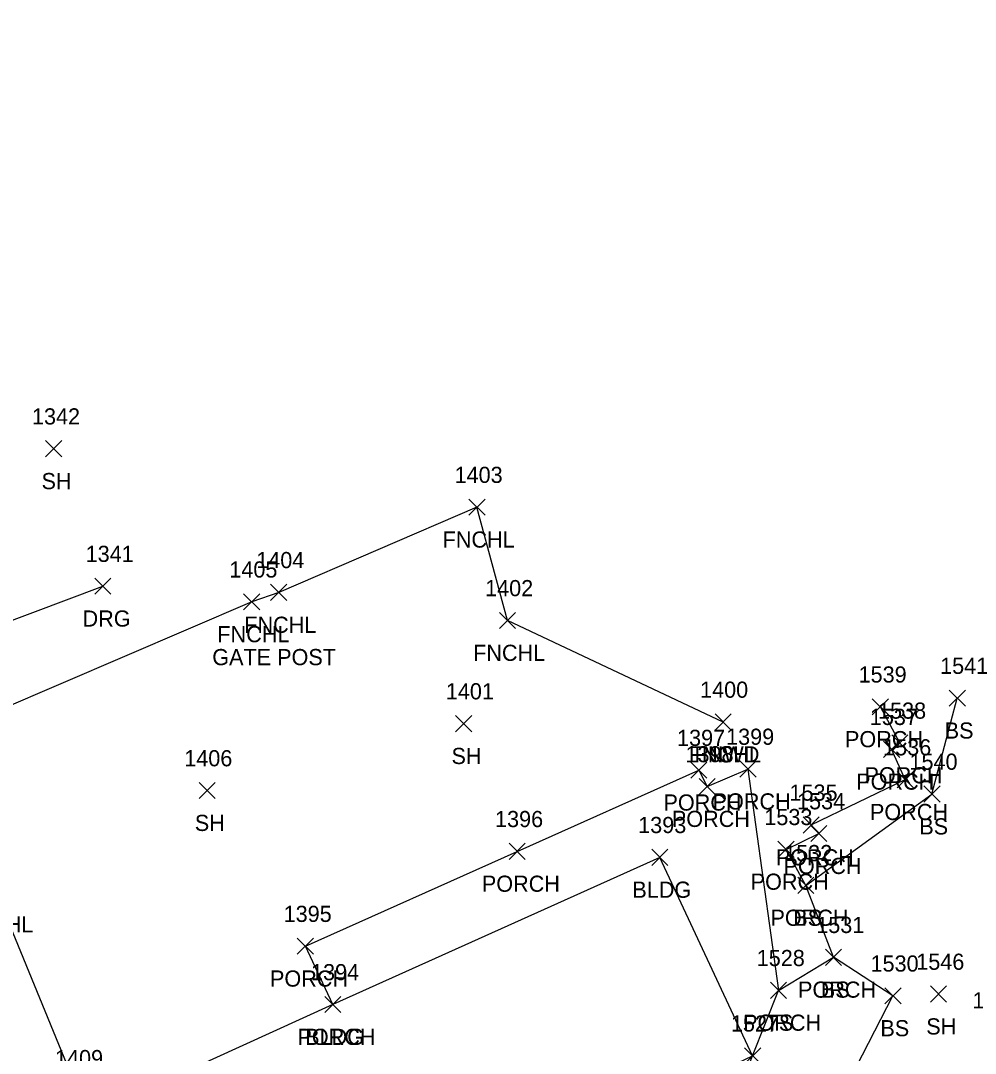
# Model space of a CAD drawing. Extents: x 1504228 to 1506103, y 437717 to 440106.
# Drawn here: x 1505212.8 to 1505331, y 438311.9 to 438439.6 of the extents above; entities that cross this region are included whole.
import ezdxf

# ---------------------------------------------------------------- set-up
doc = ezdxf.new("R2010")
doc.units = 0
for name, color, linetype in [('L_A', 7, 'Continuous'), ('L_C', 7, 'Continuous'), ('L_I', 7, 'Continuous'), ('L_TIC', 7, 'Continuous'), ('LBC', 7, 'Continuous'), ('LBF', 7, 'Continuous'), ('LELB', 7, 'Continuous'), ('LFNC', 7, 'Continuous'), ('R_A', 7, 'Continuous'), ('R_I', 7, 'Continuous'), ('R_TIC', 7, 'Continuous'), ('RDG', 7, 'Continuous')]:
    doc.layers.add(name, color=color, linetype=linetype)

msp = doc.modelspace()

# ---------------------------------------------------------------- linework, layer by layer
at = {"layer": 'L_TIC'}
for points in [[(1505215.93, 438385.69), (1505217.93, 438387.69)], [(1505217.93, 438385.69), (1505215.93, 438387.69)], [(1505268.3, 438378.46), (1505270.3, 438380.46)], [(1505270.3, 438378.46), (1505268.3, 438380.46)], [(1505243.77, 438367.92), (1505245.77, 438369.92)], [(1505245.77, 438367.92), (1505243.77, 438369.92)], [(1505240.43, 438366.76), (1505242.43, 438368.76)], [(1505242.43, 438366.76), (1505240.43, 438368.76)], [(1505272.09, 438364.45), (1505274.09, 438366.45)], [(1505274.09, 438364.45), (1505272.09, 438366.45)], [(1505327.74, 438354.84), (1505329.74, 438356.84)], [(1505329.74, 438354.84), (1505327.74, 438356.84)], [(1505318.22, 438353.77), (1505320.22, 438355.77)], [(1505320.22, 438353.77), (1505318.22, 438355.77)], [(1505266.66, 438351.69), (1505268.66, 438353.69)], [(1505268.66, 438351.69), (1505266.66, 438353.69)], [(1505298.77, 438351.89), (1505300.77, 438353.89)], [(1505300.77, 438351.89), (1505298.77, 438353.89)], [(1505298.77, 438351.89), (1505300.77, 438353.89)], [(1505300.77, 438351.89), (1505298.77, 438353.89)], [(1505320.63, 438349.3), (1505322.63, 438351.3)], [(1505322.63, 438349.3), (1505320.63, 438351.3)], [(1505319.61, 438348.52), (1505321.61, 438350.52)], [(1505321.61, 438348.52), (1505319.61, 438350.52)], [(1505295.76, 438345.93), (1505297.76, 438347.93)], [(1505297.76, 438345.93), (1505295.76, 438347.93)], [(1505301.83, 438346.07), (1505303.83, 438348.07)], [(1505303.83, 438346.07), (1505301.83, 438348.07)], [(1505321.3, 438344.76), (1505323.3, 438346.76)], [(1505323.3, 438344.76), (1505321.3, 438346.76)], [(1505234.91, 438343.41), (1505236.91, 438345.41)], [(1505236.91, 438343.41), (1505234.91, 438345.41)], [(1505296.79, 438343.91), (1505298.79, 438345.91)], [(1505298.79, 438343.91), (1505296.79, 438345.91)], [(1505324.6, 438342.98), (1505326.6, 438344.98)], [(1505326.6, 438342.98), (1505324.6, 438344.98)], [(1505309.66, 438339.16), (1505311.66, 438341.16)], [(1505311.66, 438339.16), (1505309.66, 438341.16)], [(1505310.61, 438338.09), (1505312.61, 438340.09)], [(1505312.61, 438338.09), (1505310.61, 438340.09)], [(1505273.28, 438335.89), (1505275.28, 438337.89)], [(1505275.28, 438335.89), (1505273.28, 438337.89)], [(1505290.94, 438335.15), (1505292.94, 438337.15)], [(1505292.94, 438335.15), (1505290.94, 438337.15)], [(1505290.94, 438335.15), (1505292.94, 438337.15)], [(1505292.94, 438335.15), (1505290.94, 438337.15)], [(1505306.55, 438336.14), (1505308.55, 438338.14)], [(1505308.55, 438336.14), (1505306.55, 438338.14)], [(1505309, 438331.68), (1505311, 438333.68)], [(1505311, 438331.68), (1505309, 438333.68)], [(1505309, 438331.68), (1505311, 438333.68)], [(1505311, 438331.68), (1505309, 438333.68)], [(1505247.07, 438324.16), (1505249.07, 438326.16)], [(1505249.07, 438324.16), (1505247.07, 438326.16)], [(1505312.41, 438322.79), (1505314.41, 438324.79)], [(1505314.41, 438322.79), (1505312.41, 438324.79)], [(1505312.41, 438322.79), (1505314.41, 438324.79)], [(1505314.41, 438322.79), (1505312.41, 438324.79)], [(1505305.61, 438318.7), (1505307.61, 438320.7)], [(1505307.61, 438318.7), (1505305.61, 438320.7)], [(1505305.61, 438318.7), (1505307.61, 438320.7)], [(1505307.61, 438318.7), (1505305.61, 438320.7)], [(1505319.78, 438318.02), (1505321.78, 438320.02)], [(1505321.78, 438318.02), (1505319.78, 438320.02)], [(1505325.41, 438318.24), (1505327.41, 438320.24)], [(1505327.41, 438318.24), (1505325.41, 438320.24)], [(1505250.46, 438316.95), (1505252.46, 438318.95)], [(1505252.46, 438316.95), (1505250.46, 438318.95)], [(1505250.46, 438316.95), (1505252.46, 438318.95)], [(1505252.46, 438316.95), (1505250.46, 438318.95)], [(1505302.41, 438310.6), (1505304.41, 438312.6)], [(1505304.41, 438310.6), (1505302.41, 438312.6)], [(1505302.41, 438310.6), (1505304.41, 438312.6)], [(1505304.41, 438310.6), (1505302.41, 438312.6)]]:
    msp.add_lwpolyline(points, dxfattribs=at)
at = {"layer": 'LBC'}
for points in [[(1505291.94, 438336.15), (1505251.46, 438317.95), (1505221.32, 438304.23), (1505215.36, 438301.39), (1505212.86, 438300.1), (1505216.77, 438291.38), (1505219.71, 438285.09), (1505224.14, 438275.75), (1505225.84, 438276.51), (1505226.05, 438276.61), (1505237.29, 438281.5), (1505257.32, 438290.64), (1505259.92, 438292.17), (1505266.3, 438278.35), (1505276.69, 438282.9), (1505286.75, 438287.54), (1505280.28, 438300.6), (1505303.41, 438311.6)], [(1505303.41, 438311.6), (1505291.94, 438336.15)]]:
    msp.add_lwpolyline(points, dxfattribs=at)
at = {"layer": 'LBF'}
msp.add_lwpolyline([(1505251.46, 438317.95), (1505248.07, 438325.16), (1505274.28, 438336.89), (1505296.76, 438346.93), (1505297.79, 438344.91), (1505302.83, 438347.07), (1505306.61, 438319.7), (1505313.41, 438323.79), (1505310, 438332.68), (1505307.55, 438337.14), (1505311.61, 438339.09), (1505310.66, 438340.16), (1505322.3, 438345.76), (1505320.61, 438349.52), (1505321.63, 438350.3), (1505319.22, 438354.77)], dxfattribs=at)
at = {"layer": 'LELB'}
for points in [[(1505310, 438332.68), (1505325.6, 438343.98), (1505328.74, 438355.84)], [(1505219.87, 438244.66), (1505224.21, 438246.43), (1505223.77, 438248.66), (1505222.66, 438251.45), (1505223.31, 438252.49), (1505228.98, 438251.31), (1505233.48, 438250.35), (1505246.94, 438254.41), (1505264.28, 438261.06), (1505277.62, 438265.2), (1505287.87, 438271.1), (1505299.61, 438285.63), (1505311.02, 438300.11), (1505320.78, 438319.02), (1505313.41, 438323.79)], [(1505233.95, 438258.18), (1505246, 438260.65), (1505261.61, 438268.97), (1505271.35, 438273.16), (1505281.01, 438281.22), (1505294.75, 438289.38), (1505303.41, 438311.6), (1505306.61, 438319.7)]]:
    msp.add_lwpolyline(points, dxfattribs=at)
at = {"layer": 'LFNC'}
msp.add_lwpolyline([(1505299.77, 438352.89), (1505273.09, 438365.45), (1505269.3, 438379.46), (1505244.77, 438368.92), (1505241.43, 438367.76), (1505202.02, 438350.84), (1505209.75, 438331.86), (1505219.87, 438307.32), (1505221.32, 438304.23)], dxfattribs=at)
at = {"layer": 'R_TIC'}
for points in [[(1505222.01, 438368.69), (1505224.01, 438370.69)], [(1505224.01, 438368.69), (1505222.01, 438370.69)]]:
    msp.add_lwpolyline(points, dxfattribs=at)
at = {"layer": 'RDG'}
msp.add_lwpolyline([(1505169.09, 438439.64), (1505176.6, 438437.44), (1505183.39, 438415.8), (1505189.12, 438396.31), (1505196.49, 438374.95), (1505201.15, 438361.5), (1505223.01, 438369.69)], dxfattribs=at)

# ---------------------------------------------------------------- texts
at = {"layer": 'L_A'}
for s, p in [('SH', (1505215.42, 438381.69)), ('FNCHL', (1505265.05, 438374.46)), ('FNCHL', (1505240.51, 438363.92)), ('FNCHL', (1505237.18, 438362.76)), ('FNCHL', (1505268.83, 438360.45)), ('BS', (1505327.18, 438350.84)), ('PORCH', (1505314.84, 438349.77)), ('FNCHL', (1505295.52, 438347.89)), ('FNWD', (1505296.23, 438347.89)), ('SH', (1505266.15, 438347.69)), ('PORCH', (1505317.25, 438345.3)), ('PORCH', (1505316.23, 438344.52)), ('PORCH', (1505292.38, 438341.93)), ('PORCH', (1505298.46, 438342.07)), ('PORCH', (1505317.93, 438340.76)), ('SH', (1505234.39, 438339.41)), ('PORCH', (1505293.42, 438339.91)), ('BS', (1505324.04, 438338.98)), ('PORCH', (1505306.28, 438335.16)), ('PORCH', (1505307.23, 438334.09)), ('PORCH', (1505269.91, 438331.89)), ('BLDG', (1505288.53, 438331.15)), ('BLDG', (1505288.53, 438331.15)), ('PORCH', (1505303.17, 438332.14)), ('PORCH', (1505305.62, 438327.68)), ('BS', (1505308.44, 438327.68)), ('FNCHL', (1505205.5, 438326.86)), ('PORCH', (1505243.69, 438320.16)), ('PORCH', (1505309.03, 438318.79)), ('BS', (1505311.85, 438318.79)), ('PORCH', (1505302.23, 438314.7)), ('TS', (1505305.02, 438314.7)), ('BS', (1505319.22, 438314.02)), ('SH', (1505324.9, 438314.24)), ('PORCH', (1505247.09, 438312.95)), ('BLDG', (1505248.05, 438312.95))]:
    msp.add_text(s, height=2, dxfattribs=at).set_placement(p)
at = {"layer": 'L_C'}
msp.add_text('GATE POST', height=2, dxfattribs=at).set_placement((1505236.55, 438359.92))
at = {"layer": 'L_I'}
for s, p in [('1342', (1505214.24, 438389.69)), ('1403', (1505266.53, 438382.46)), ('1405', (1505238.66, 438370.76)), ('1404', (1505241.99, 438371.92)), ('1402', (1505270.31, 438368.45)), ('1541', (1505326.61, 438358.84)), ('1539', (1505316.52, 438357.77)), ('1401', (1505265.45, 438355.69)), ('1400', (1505296.91, 438355.89)), ('1400', (1505296.91, 438355.89)), ('1538', (1505318.93, 438353.3)), ('1537', (1505317.91, 438352.52)), ('1397', (1505294.06, 438349.93)), ('1399', (1505300.13, 438350.07)), ('1398', (1505295.1, 438347.91)), ('1536', (1505319.56, 438348.76)), ('1406', (1505233.08, 438347.41)), ('1540', (1505322.82, 438346.98)), ('1535', (1505307.97, 438343.16)), ('1534', (1505308.91, 438342.09)), ('1533', (1505304.86, 438340.14)), ('1396', (1505271.54, 438339.89)), ('1393', (1505289.25, 438339.15)), ('1393', (1505289.25, 438339.15)), ('1532', (1505307.31, 438335.68)), ('1532', (1505307.31, 438335.68)), ('1395', (1505245.38, 438328.16)), ('1531', (1505311.28, 438326.79)), ('1531', (1505311.28, 438326.79)), ('1528', (1505303.92, 438322.7)), ('1528', (1505303.92, 438322.7)), ('1546', (1505323.66, 438322.24)), ('1394', (1505248.77, 438320.95)), ('1394', (1505248.77, 438320.95)), ('1530', (1505318, 438322.02)), ('1544', (1505330.61, 438317.46)), ('1527', (1505300.72, 438314.6)), ('1527', (1505300.72, 438314.6)), ('1409', (1505217.09, 438310.32)), ('1409', (1505217.09, 438310.32))]:
    msp.add_text(s, height=2, dxfattribs=at).set_placement(p)
at = {"layer": 'R_A'}
msp.add_text('DRG', height=2, dxfattribs=at).set_placement((1505220.5, 438364.69))
at = {"layer": 'R_I'}
msp.add_text('1341', height=2, dxfattribs=at).set_placement((1505220.88, 438372.69))

doc.saveas('drawing.dxf')
